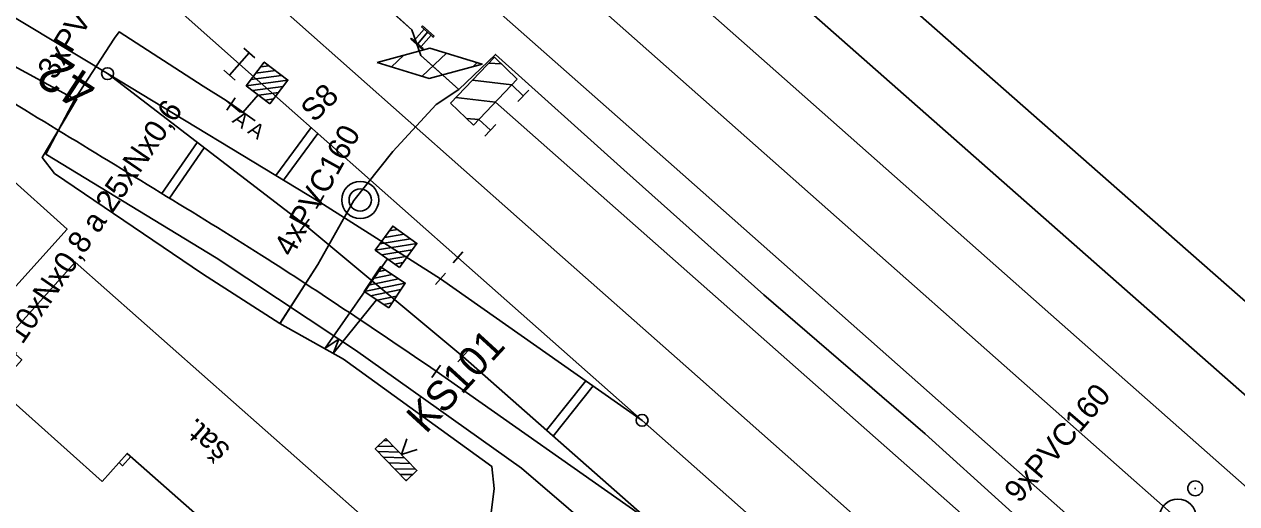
# Model space of a CAD drawing. Extents: x -496570 to -495506, y -1089156 to -1088046.
# Drawn here: x -496267.2 to -496185.7, y -1088424.9 to -1088392.7 of the extents above; entities that cross this region are included whole.
import ezdxf

# ---------------------------------------------------------------- set-up
doc = ezdxf.new("R2010")
doc.units = 0
for name, color, linetype in [('11', 7, 'Continuous'), ('14', 7, 'Continuous'), ('15', 7, 'Continuous'), ('20', 7, 'Continuous'), ('27', 7, 'Continuous'), ('35', 7, 'Continuous'), ('39', 7, 'Continuous'), ('54', 7, 'Continuous'), ('PŘÍSTUPOVÉ_CESTY', 7, 'Continuous'), ('PŮVODNÍ_NÁVRH', 7, 'Continuous'), ('SEE', 7, 'Continuous')]:
    doc.layers.add(name, color=color, linetype=linetype)

msp = doc.modelspace()

# ---------------------------------------------------------------- linework, layer by layer
at = {"layer": '11'}
for p, q in [((-496247.915, -1088399.62), (-496250.285, -1088402.84)), ((-496247.464, -1088400.02), (-496249.769, -1088403.152)), ((-496257.953, -1088404.05), (-496255.579, -1088400.616)), ((-496257.439, -1088404.362), (-496255.102, -1088400.982)), ((-496232.102, -1088419.979), (-496229.473, -1088416.647)), ((-496231.651, -1088420.377), (-496228.982, -1088416.993)), ((-496188.574, -1088423.886), (-496188.474, -1088423.886))]:
    msp.add_line(p, q, dxfattribs=at)
for centre, radius in [((-496244.623, -1088404.492), 1.246), ((-496244.623, -1088404.492), 0.752), ((-496188.524, -1088423.886), 0.5), ((-496189.691, -1088425.858), 1.246)]:
    msp.add_circle(centre, radius, dxfattribs=at)
at = {"layer": '14'}
for points in [[(-496500.326, -1088150.883), (-496478.319, -1088170.391), (-496459.205, -1088187.309), (-496440.603, -1088203.768), (-496419.398, -1088222.532), (-496401.337, -1088238.524), (-496381.863, -1088255.763), (-496363.496, -1088272.022), (-496344.908, -1088288.479), (-496325.602, -1088305.577), (-496305.115, -1088323.698), (-496285.279, -1088341.274), (-496267.778, -1088356.78), (-496248.642, -1088373.733), (-496220.391, -1088398.759), (-496201.351, -1088415.62), (-496182.974, -1088431.889), (-496164.259, -1088448.462), (-496145.687, -1088464.902), (-496132.984, -1088476.226), (-496115.09, -1088492.058), (-496092.682, -1088511.89), (-496073.961, -1088528.378)], [(-496111.45, -1088501.61), (-496112.796, -1088500.414), (-496116.847, -1088496.777), (-496137.726, -1088478.277), (-496158.004, -1088460.314), (-496179.39, -1088441.364), (-496198.571, -1088424.361), (-496223.52, -1088402.267), (-496247.329, -1088381.198), (-496269.626, -1088361.454), (-496288.304, -1088344.927), (-496319.947, -1088316.905), (-496344.485, -1088295.207), (-496348.139, -1088291.966), (-496366.841, -1088275.405), (-496385.169, -1088259.187), (-496404.395, -1088242.153), (-496422.154, -1088226.434), (-496443.818, -1088207.26), (-496462.548, -1088190.678), (-496481.576, -1088173.849), (-496503.417, -1088154.088)], [(-496036.118, -1088555.5), (-496048.975, -1088544.1), (-496066.196, -1088528.906), (-496086.152, -1088511.349), (-496104.929, -1088494.746), (-496123.588, -1088478.229), (-496142.293, -1088461.701), (-496160.965, -1088445.175), (-496179.891, -1088428.396), (-496198.214, -1088412.189), (-496217.292, -1088395.311), (-496245.811, -1088370.064), (-496264.918, -1088353.145), (-496281.988, -1088338.018), (-496302.247, -1088320.079), (-496322.57, -1088302.076), (-496341.966, -1088284.907), (-496360.552, -1088268.447), (-496378.713, -1088252.378), (-496398.4, -1088234.928), (-496416.447, -1088218.945), (-496437.668, -1088200.162), (-496456.103, -1088183.845), (-496474.042, -1088168.071)], [(-496082.486, -1088502.043), (-496098.63, -1088487.696), (-496117.358, -1088471.138), (-496136.056, -1088454.602), (-496154.785, -1088438.063), (-496173.551, -1088421.521), (-496192.303, -1088405.013), (-496211.05, -1088388.494), (-496229.814, -1088371.969), (-496241.71, -1088361.483), (-496259.312, -1088345.98), (-496335.952, -1088278.18), (-496354.664, -1088261.608), (-496372.853, -1088245.502), (-496392.083, -1088228.459), (-496410.817, -1088211.882), (-496431.795, -1088193.31), (-496448.334, -1088178.663)], [(-496465.102, -1088201.03), (-496456.086, -1088209.031), (-496439.8, -1088223.453), (-496418.031, -1088242.716), (-496400.164, -1088258.552), (-496382.525, -1088274.174), (-496378.001, -1088278.141), (-496364.605, -1088290.03), (-496358.266, -1088295.605), (-496338.75, -1088312.899), (-496318.462, -1088330.866), (-496297.237, -1088349.647), (-496278.02, -1088366.672), (-496252.626, -1088389.158), (-496233.92, -1088405.779), (-496222.755, -1088415.674), (-496210.969, -1088426.126), (-496208.778, -1088428.033)], [(-496419.776, -1088210.17), (-496413.73, -1088215.561), (-496395.384, -1088231.799), (-496375.938, -1088249.024), (-496357.661, -1088265.193), (-496339.088, -1088281.642), (-496320.817, -1088297.785), (-496278.447, -1088335.251), (-496262.212, -1088349.594), (-496242.734, -1088366.795), (-496214.147, -1088392.048), (-496195.339, -1088408.643), (-496176.8, -1088425.002), (-496157.997, -1088441.59), (-496139.148, -1088458.239), (-496120.509, -1088474.69), (-496101.775, -1088491.246), (-496088.913, -1088502.664), (-496081.326, -1088509.353), (-496072.768, -1088516.905)], [(-496238.055, -1088408.352), (-496252.739, -1088395.349), (-496269.088, -1088380.829), (-496284.933, -1088366.798), (-496289.774, -1088362.518), (-496304.914, -1088349.103), (-496331.751, -1088325.354), (-496382.404, -1088280.635)], [(-496225.685, -1088419.311), (-496239.228, -1088409.789), (-496247.333, -1088404.627), (-496261.601, -1088395.991), (-496275.815, -1088387.388)], [(-496174.593, -1088471.013), (-496192.559, -1088454.988), (-496206.347, -1088442.759), (-496213.463, -1088436.447), (-496216.342, -1088433.89), (-496225.123, -1088426.139), (-496237.731, -1088415.01), (-496248.348, -1088406.17), (-496261.601, -1088395.991)], [(-496235.541, -1088397.911), (-496201.57, -1088427.952), (-496171.826, -1088454.349)], [(-496209.306, -1088433.861), (-496213.249, -1088430.329), (-496225.685, -1088419.311), (-496238.055, -1088408.352)], [(-496225.123, -1088426.139), (-496239.518, -1088416.014)]]:
    msp.add_lwpolyline(points, dxfattribs=at)
msp.add_spline([(-496239.518, -1088416.014), (-496251.238, -1088408.214), (-496258.061, -1088403.984), (-496271.935, -1088395.519)], degree=3, dxfattribs=at)
at = {"layer": '15'}
for p, q in [((-496251.702, -1088394.932), (-496252.45, -1088394.269)), ((-496253.402, -1088396.097), (-496252.076, -1088394.601)), ((-496253.028, -1088396.429), (-496253.776, -1088395.766)), ((-496250.324, -1088395.784), (-496251.64, -1088395.96)), ((-496250.745, -1088395.462), (-496251.318, -1088395.539)), ((-496249.481, -1088396.428), (-496252.284, -1088396.803)), ((-496249.902, -1088396.106), (-496251.963, -1088396.382)), ((-496249.803, -1088396.849), (-496251.863, -1088397.125)), ((-496250.125, -1088397.271), (-496251.442, -1088397.447)), ((-496250.447, -1088397.692), (-496251.02, -1088397.769)), ((-496242.109, -1088406.482), (-496242.68, -1088406.575)), ((-496241.249, -1088407.103), (-496243.301, -1088407.435)), ((-496241.679, -1088406.792), (-496242.99, -1088407.004)), ((-496240.819, -1088407.413), (-496243.611, -1088407.865)), ((-496241.129, -1088407.843), (-496243.181, -1088408.175)), ((-496241.44, -1088408.274), (-496242.751, -1088408.486)), ((-496241.75, -1088408.703), (-496242.321, -1088408.796)), ((-496242.042, -1088409.784), (-496244.077, -1088410.209)), ((-496242.486, -1088409.493), (-496243.786, -1088409.765)), ((-496242.93, -1088409.203), (-496243.496, -1088409.321)), ((-496241.598, -1088410.074), (-496244.367, -1088410.653)), ((-496241.888, -1088410.517), (-496243.923, -1088410.943)), ((-496242.179, -1088410.962), (-496243.479, -1088411.233)), ((-496242.469, -1088411.405), (-496243.035, -1088411.524))]:
    msp.add_line(p, q, dxfattribs=at)
for points in [[(-496250.696, -1088398.017), (-496252.284, -1088396.803), (-496251.07, -1088395.214), (-496249.481, -1088396.428)], [(-496250.696, -1088398.017), (-496252.284, -1088396.803), (-496251.07, -1088395.214), (-496249.481, -1088396.428)], [(-496241.989, -1088409.035), (-496243.611, -1088407.865), (-496242.441, -1088406.243), (-496240.819, -1088407.413)], [(-496241.989, -1088409.035), (-496243.611, -1088407.865), (-496242.441, -1088406.243), (-496240.819, -1088407.413)], [(-496242.693, -1088411.747), (-496244.367, -1088410.653), (-496243.272, -1088408.979), (-496241.598, -1088410.074)], [(-496242.693, -1088411.747), (-496244.367, -1088410.653), (-496243.272, -1088408.979), (-496241.598, -1088410.074)]]:
    msp.add_lwpolyline(points, close=True, dxfattribs=at)
for points in [[(-496250.696, -1088398.017), (-496252.284, -1088396.803), (-496251.07, -1088395.214), (-496249.481, -1088396.428), (-496250.696, -1088398.017)], [(-496250.696, -1088398.017), (-496252.284, -1088396.803), (-496251.07, -1088395.214), (-496249.481, -1088396.428), (-496250.696, -1088398.017)], [(-496241.989, -1088409.035), (-496243.611, -1088407.865), (-496242.441, -1088406.243), (-496240.819, -1088407.413), (-496241.989, -1088409.035)], [(-496241.989, -1088409.035), (-496243.611, -1088407.865), (-496242.441, -1088406.243), (-496240.819, -1088407.413), (-496241.989, -1088409.035)], [(-496242.693, -1088411.747), (-496244.367, -1088410.653), (-496243.272, -1088408.979), (-496241.598, -1088410.074), (-496242.693, -1088411.747)], [(-496242.693, -1088411.747), (-496244.367, -1088410.653), (-496243.272, -1088408.979), (-496241.598, -1088410.074), (-496242.693, -1088411.747)]]:
    msp.add_lwpolyline(points, dxfattribs=at)
at = {"layer": '20'}
for p, q in [((-496253.015, -1088397.619), (-496253.585, -1088398.441)), ((-496251.673, -1088399.159), (-496253.3, -1088398.03))]:
    msp.add_line(p, q, dxfattribs=at)
at = {"layer": '27'}
for p, q in [((-496247.074, -1088404.199), (-496247.592, -1088405.055)), ((-496248.043, -1088405.774), (-496248.653, -1088406.566)), ((-496238.387, -1088408.726), (-496237.723, -1088407.978)), ((-496239.559, -1088410.164), (-496238.897, -1088409.414)), ((-496238.062, -1088415.385), (-496237.4, -1088414.635)), ((-496239.805, -1088416.423), (-496239.231, -1088415.605))]:
    msp.add_line(p, q, dxfattribs=at)
for points in [[(-496275.815, -1088387.388), (-496261.601, -1088395.991), (-496247.333, -1088404.627)], [(-496261.601, -1088395.991), (-496248.348, -1088406.17)], [(-496225.685, -1088419.311), (-496239.228, -1088409.789)], [(-496216.342, -1088433.89), (-496225.123, -1088426.139), (-496237.731, -1088415.01)], [(-496225.123, -1088426.139), (-496239.518, -1088416.014)]]:
    msp.add_lwpolyline(points, dxfattribs=at)
for centre in [(-496261.601, -1088395.991), (-496225.685, -1088419.311)]:
    msp.add_circle(centre, 0.4, dxfattribs=at)
at = {"layer": '35'}
for p, q in [((-496238.557, -1088397.981), (-496235.611, -1088394.895)), ((-496235.611, -1088394.895), (-496234.068, -1088396.368)), ((-496235.979, -1088395.281), (-496235.148, -1088395.337)), ((-496234.436, -1088396.754), (-496237.084, -1088396.438)), ((-496237.014, -1088399.454), (-496234.068, -1088396.368)), ((-496234.436, -1088396.754), (-496233.665, -1088397.49)), ((-496238.189, -1088397.595), (-496235.541, -1088397.911)), ((-496234.034, -1088397.876), (-496233.297, -1088397.104)), ((-496237.014, -1088399.454), (-496238.557, -1088397.981)), ((-496236.646, -1088399.068), (-496237.477, -1088399.012)), ((-496235.875, -1088399.804), (-496236.646, -1088399.068)), ((-496236.646, -1088399.068), (-496236.646, -1088399.068)), ((-496236.243, -1088400.19), (-496235.506, -1088399.418))]:
    msp.add_line(p, q, dxfattribs=at)
at = {"layer": '39'}
for p, q in [((-496240.994, -1088393.771), (-496240.322, -1088393.003)), ((-496240.762, -1088393.976), (-496240.105, -1088393.198)), ((-496240.537, -1088394.175), (-496239.867, -1088393.412)), ((-496240.501, -1088392.843), (-496240.447, -1088392.781)), ((-496240.501, -1088392.843), (-496239.723, -1088393.542)), ((-496239.727, -1088393.537), (-496240.501, -1088392.843)), ((-496240.447, -1088392.781), (-496239.662, -1088393.474)), ((-496239.662, -1088393.474), (-496239.727, -1088393.537)), ((-496241.179, -1088393.608), (-496241.228, -1088393.671)), ((-496241.228, -1088393.671), (-496240.443, -1088394.369)), ((-496241.179, -1088393.608), (-496240.391, -1088394.297)), ((-496240.384, -1088394.31), (-496241.179, -1088393.608)), ((-496240.443, -1088394.369), (-496240.384, -1088394.31))]:
    msp.add_line(p, q, dxfattribs=at)
for points in [[(-496270.398, -1088413.199), (-496264.319, -1088406.454), (-496268.54, -1088402.65), (-496268.109, -1088402.133), (-496273.976, -1088396.875), (-496274.471, -1088396.883), (-496275.403, -1088397.88), (-496278.797, -1088394.71), (-496279.327, -1088395.258), (-496281.591, -1088393.068), (-496284.121, -1088396.139), (-496286.79, -1088393.94), (-496286.631, -1088393.747), (-496287.972, -1088392.629), (-496290.06, -1088395.029), (-496290.69, -1088394.461), (-496290.624, -1088394.387), (-496297.006, -1088388.637), (-496299.062, -1088386.784), (-496316.329, -1088371.229), (-496318.738, -1088373.773), (-496329.498, -1088364.171), (-496331.093, -1088365.84)], [(-496239.727, -1088393.537), (-496239.723, -1088393.542), (-496239.662, -1088393.474), (-496239.662, -1088393.474)], [(-496240.443, -1088394.369), (-496240.452, -1088394.376), (-496240.391, -1088394.297), (-496240.384, -1088394.31)], [(-496261.958, -1088423.433), (-496269.031, -1088417.102), (-496267.367, -1088415.244), (-496268.641, -1088414.103), (-496263.772, -1088408.664), (-496244.63, -1088425.633), (-496246.068, -1088427.269), (-496244.762, -1088428.416), (-496247.293, -1088431.247), (-496248.615, -1088430.059), (-496249.511, -1088431.056), (-496260.279, -1088421.534), (-496261.958, -1088423.433)], [(-496260.04, -1088421.746), (-496260.589, -1088422.368), (-496260.829, -1088422.156)]]:
    msp.add_lwpolyline(points, dxfattribs=at)
at = {"layer": '54'}
for p, q in [((-496246.98, -1088414.46), (-496242.8, -1088408.45)), ((-496246.45, -1088414.81), (-496243.53, -1088411.2)), ((-496246.98, -1088414.46), (-496246.057, -1088413.842)), ((-496246.45, -1088414.81), (-496246.057, -1088413.842))]:
    msp.add_line(p, q, dxfattribs=at)
for points in [[(-496371.11, -1088280.23), (-496365.46, -1088285.379), (-496354.51, -1088295.443), (-496342.857, -1088305.764), (-496340.38, -1088305.964), (-496338.669, -1088307.53), (-496337.881, -1088310.154), (-496321.648, -1088324.528), (-496300.521, -1088343.235), (-496298.05, -1088343.439), (-496296.295, -1088345.046), (-496295.304, -1088347.848), (-496283.364, -1088358.425), (-496270.673, -1088369.666), (-496252.528, -1088385.701), (-496249.196, -1088385.882), (-496241.162, -1088393.056), (-496240.55, -1088394.77)], [(-496272.174, -1088393.151), (-496263.798, -1088397.711), (-496265.754, -1088401.402), (-496254.295, -1088408.39), (-496246.057, -1088413.842), (-496244.939, -1088414.582), (-496233.784, -1088422.533), (-496221.15, -1088433.38), (-496220.602, -1088433.731), (-496217.31, -1088437.14), (-496214.3, -1088439.56), (-496212.93, -1088440.9), (-496205.07, -1088447.94), (-496205.71, -1088448.76), (-496207.72, -1088451.67), (-496206.35, -1088453.21)], [(-496263.798, -1088397.711), (-496261.126, -1088393.6), (-496260.83, -1088393.19), (-496255.17, -1088396.83), (-496253.64, -1088397.8), (-496253.3, -1088398.03)], [(-496240.55, -1088394.77), (-496237.99, -1088397.05), (-496235.53, -1088394.7), (-496226.92, -1088402.46), (-496217.51, -1088410.88), (-496206.66, -1088420.23), (-496201.26, -1088425.11), (-496190.86, -1088434.52), (-496173.69, -1088449.93), (-496166.99, -1088455.74), (-496166.15, -1088456.51), (-496151.36, -1088469.35), (-496147.46, -1088472.55), (-496145.16, -1088474.43), (-496138.22, -1088480.69), (-496138.14, -1088480.81), (-496141.67, -1088485)], [(-496253.64, -1088397.8), (-496252.71, -1088398.56), (-496252.52, -1088398.61), (-496251.49, -1088397.41)]]:
    msp.add_lwpolyline(points, dxfattribs=at)
at = {"layer": 'PŘÍSTUPOVÉ_CESTY'}
for p, q in [((-496243.437, -1088421.042), (-496242.379, -1088421.061)), ((-496243.056, -1088420.674), (-496242.747, -1088420.679)), ((-496243.425, -1088421.417), (-496242.011, -1088421.443)), ((-496243.057, -1088421.799), (-496241.643, -1088421.824)), ((-496242.689, -1088422.18), (-496241.275, -1088422.206)), ((-496242.32, -1088422.562), (-496240.906, -1088422.588)), ((-496241.952, -1088422.944), (-496241.104, -1088422.959)), ((-496241.584, -1088423.325), (-496241.485, -1088423.327))]:
    msp.add_line(p, q, dxfattribs=at)
msp.add_lwpolyline([(-496242.899, -1088420.522), (-496240.816, -1088422.681), (-496241.535, -1088423.376), (-496243.618, -1088421.217)], close=True, dxfattribs=at)
for points in [[(-496242.899, -1088420.522), (-496240.816, -1088422.681), (-496241.535, -1088423.376), (-496243.618, -1088421.217), (-496242.899, -1088420.522)], [(-496241.485, -1088420.548), (-496241.857, -1088421.602), (-496240.79, -1088421.267)]]:
    msp.add_lwpolyline(points, dxfattribs=at)
at = {"layer": 'PŮVODNÍ_NÁVRH'}
for p, q in [((-496248.178, -1088386.71), (-496241.162, -1088393.056)), ((-496263.66, -1088397.72), (-496266, -1088401.64))]:
    msp.add_line(p, q, dxfattribs=at)
for points in [[(-496265.754, -1088401.402), (-496263.798, -1088397.711), (-496261.126, -1088393.6)], [(-496250.03, -1088412.82), (-496247.47, -1088408.83), (-496245.06, -1088404.53), (-496242.43, -1088401.22), (-496239.52, -1088398.06)], [(-496250.02, -1088412.8), (-496247.47, -1088408.83), (-496245.06, -1088404.53), (-496242.43, -1088401.22), (-496239.52, -1088398.06)]]:
    msp.add_lwpolyline(points, dxfattribs=at)
at = {"layer": 'SEE'}
for p, q in [((-496242.513, -1088395.538), (-496241.7, -1088394.754)), ((-496240.451, -1088396.156), (-496238.825, -1088394.621)), ((-496237.061, -1088395.524), (-496236.764, -1088395.237))]:
    msp.add_line(p, q, dxfattribs=at)
for points in [[(-496250.02, -1088412.8), (-496247.47, -1088408.83), (-496245.06, -1088404.53), (-496242.43, -1088401.22), (-496239.52, -1088398.06), (-496237.99, -1088397.05), (-496239.964, -1088395.292), (-496240.55, -1088394.77), (-496241.162, -1088393.056), (-496248.122, -1088386.702)], [(-496272.174, -1088393.151), (-496263.798, -1088397.711), (-496263.66, -1088397.72), (-496266, -1088401.64), (-496265.17, -1088402.7), (-496255.22, -1088409.46), (-496250.02, -1088412.8), (-496245.74, -1088415.2), (-496235.79, -1088422.41), (-496235.62, -1088423.89), (-496236.05, -1088427.35)]]:
    msp.add_lwpolyline(points, dxfattribs=at)
msp.add_lwpolyline([(-496243.487, -1088395.232), (-496239.947, -1088394.274), (-496236.441, -1088395.352), (-496239.981, -1088396.31)], close=True, dxfattribs=at)

# ---------------------------------------------------------------- texts
at = {"layer": '20'}
for s, height, rotation, p in [('S8', 1.5, 44.94179, (-496247.708, -1088399.324)), ('  A A', 1, 325.23688, (-496253.891, -1088398.806))]:
    msp.add_text(s, height=height, rotation=rotation, dxfattribs=at).set_placement(p)
at = {"layer": '27'}
msp.add_text('42', height=2.5, rotation=146.92912, dxfattribs=at).set_placement((-496262.076, -1088396.511))
at = {"layer": '39'}
msp.add_text('šat.', height=1.5, rotation=138.51409, dxfattribs=at).set_placement((-496253.283, -1088421.184))
at = {"layer": '54'}
for s, rotation, p in [('3xPVC160', 59.0201, (-496265.116, -1088396.468)), ('9xPVC160', 49.41794, (-496200.345, -1088424.948))]:
    msp.add_text(s, height=1.5, rotation=rotation, dxfattribs=at).set_placement(p)
at = {"layer": 'PŘÍSTUPOVÉ_CESTY'}
msp.add_text('KS101', height=2, rotation=47.48221, dxfattribs=at).set_placement((-496240.21, -1088420.275))
at = {"layer": 'SEE'}
for s, rotation, p in [('2xspojka MK 10xNx0,8 a 25xNx0,6', 55.62336, (-496274.124, -1088424.199)), ('4xPVC160', 61.10368, (-496249.195, -1088408.387))]:
    msp.add_text(s, height=1.5, rotation=rotation, dxfattribs=at).set_placement(p)

doc.saveas('drawing.dxf')
